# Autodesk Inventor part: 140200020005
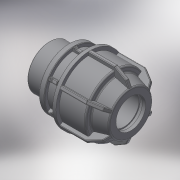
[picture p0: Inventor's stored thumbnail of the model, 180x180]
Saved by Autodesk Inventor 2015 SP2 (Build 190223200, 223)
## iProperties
Created: 2017-08
Part Number: 140200020005
Material: Generic
Description: PLASSON L.14 MALE ADAPTOR (SILVER) 20-1/2''
Document SubType Name: Modeling
Designer: KIM
Density: 1 g/cm^3
Appearance: Default
Author: KIM
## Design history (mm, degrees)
derived "140200.ipt"
feature "Solid1::140200.ipt"
tag "TaggingFeature1"
body "Solid1"
other parameters: "d4" = 15 deg, "d5" = 33, "d6" = 10.89, "d10" = 42, "d16" = 20.4, "d17" = 2.5, "d18" = 71, "d19" = 5.1, "d21" = 5.1, "d22" = 25.146, "d24" = 2.5, "d25" = 37.8, "d26" = 31.5, "d27" = 2.5, "d28" = 135 deg, "d29" = 1.5, "d31" = 1, "d44" = 0.4, "d45" = 0.6, "d46" = 150 deg, "d49" = 2.1, "d50" = 0, "d51" = 1.26, "d52" = 0.84, "d53" = 45 deg, "d54" = 21, "d55" = 8.4, "d56" = 2.1, "d57" = 0, "d58" = 0.6, "d59" = 0.4, "d61" = 360 deg, "d63" = 20.955, "d64" = 16, "d65" = 17, "d66" = 28.28925, "R_" = 20.955, "E_" = 42, "H_" = 71, "l_2" = 17
